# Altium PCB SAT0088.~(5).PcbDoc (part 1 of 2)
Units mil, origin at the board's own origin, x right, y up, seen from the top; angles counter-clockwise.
Board outline 1614.17 x 1181.1 mil, 4 copper layers (Top Layer, InternalPlane1, POWER, Bottom Layer), stack 59 mil thick; 84 components, 49 nets, 273 pads, 217 vias.
Unrouted connection lines stored in the file: 3.
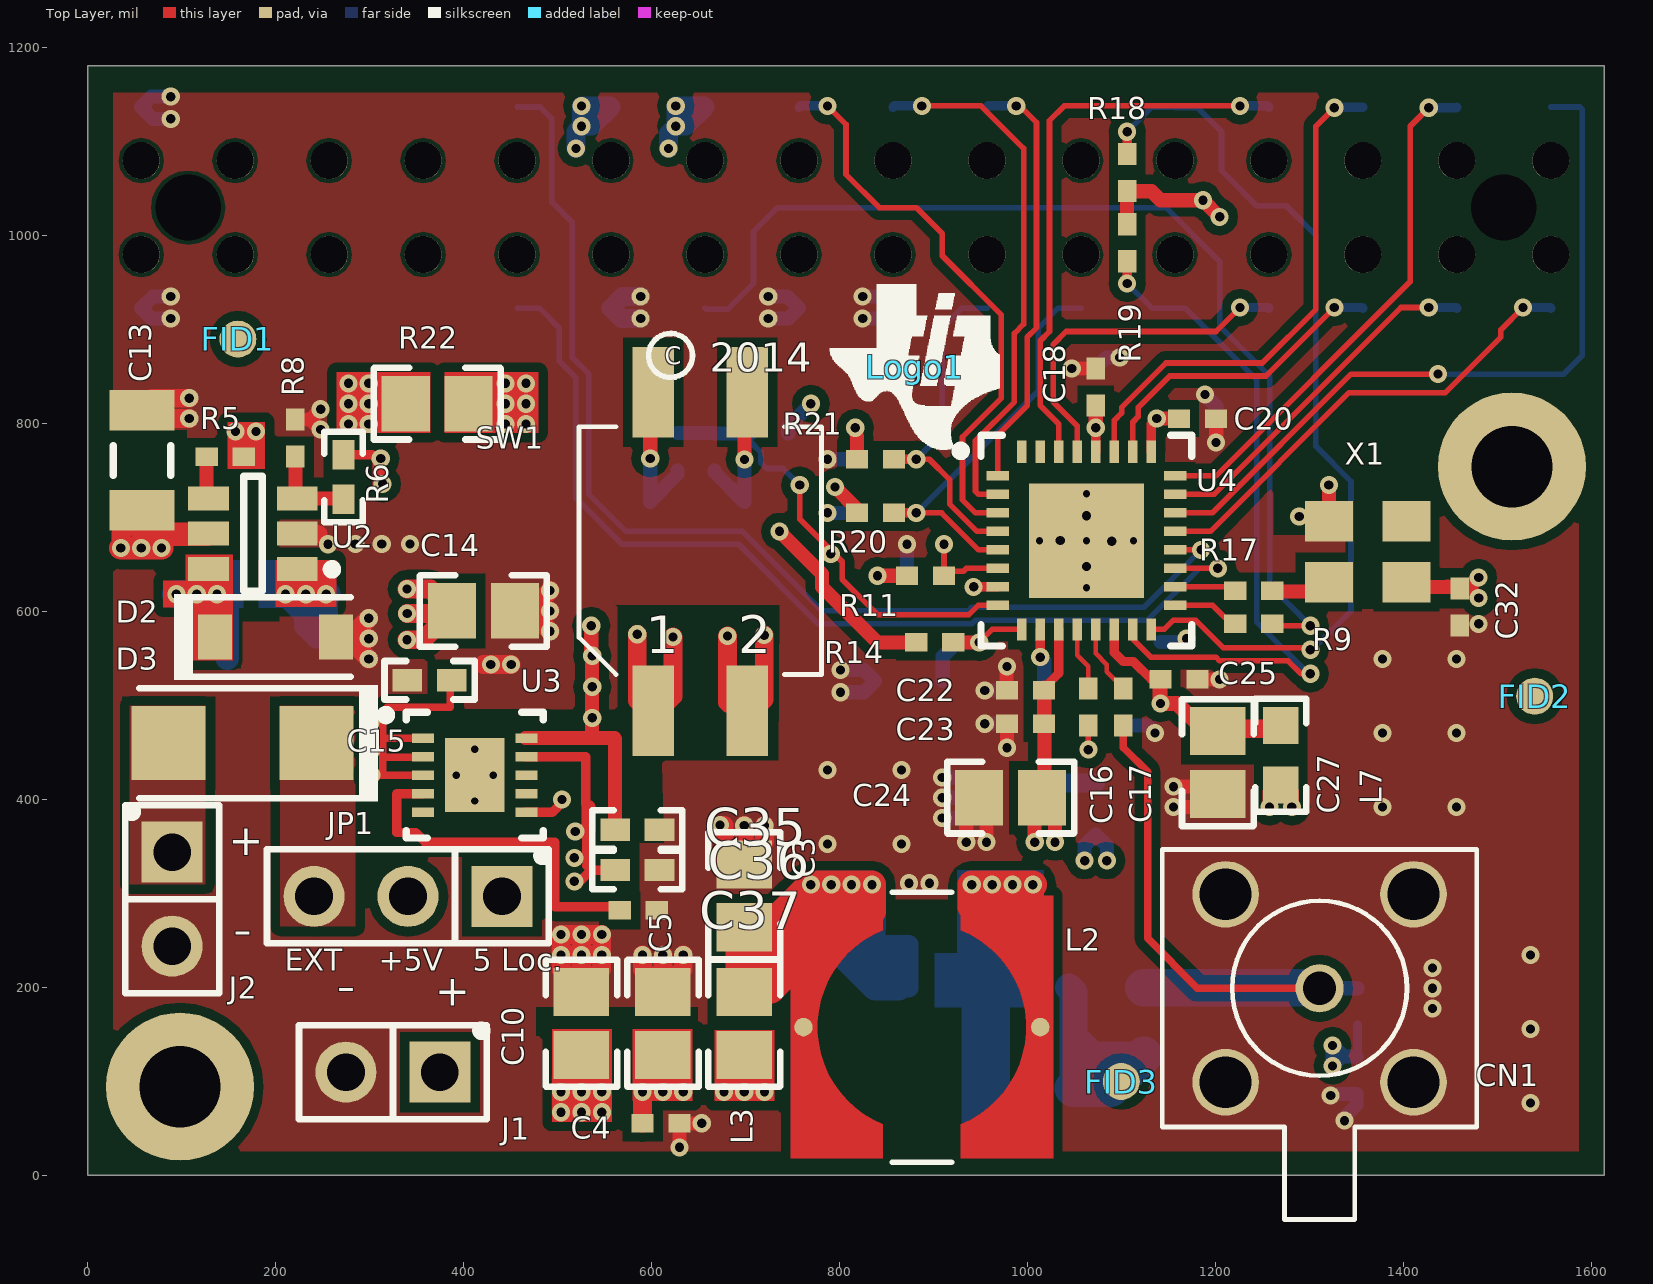
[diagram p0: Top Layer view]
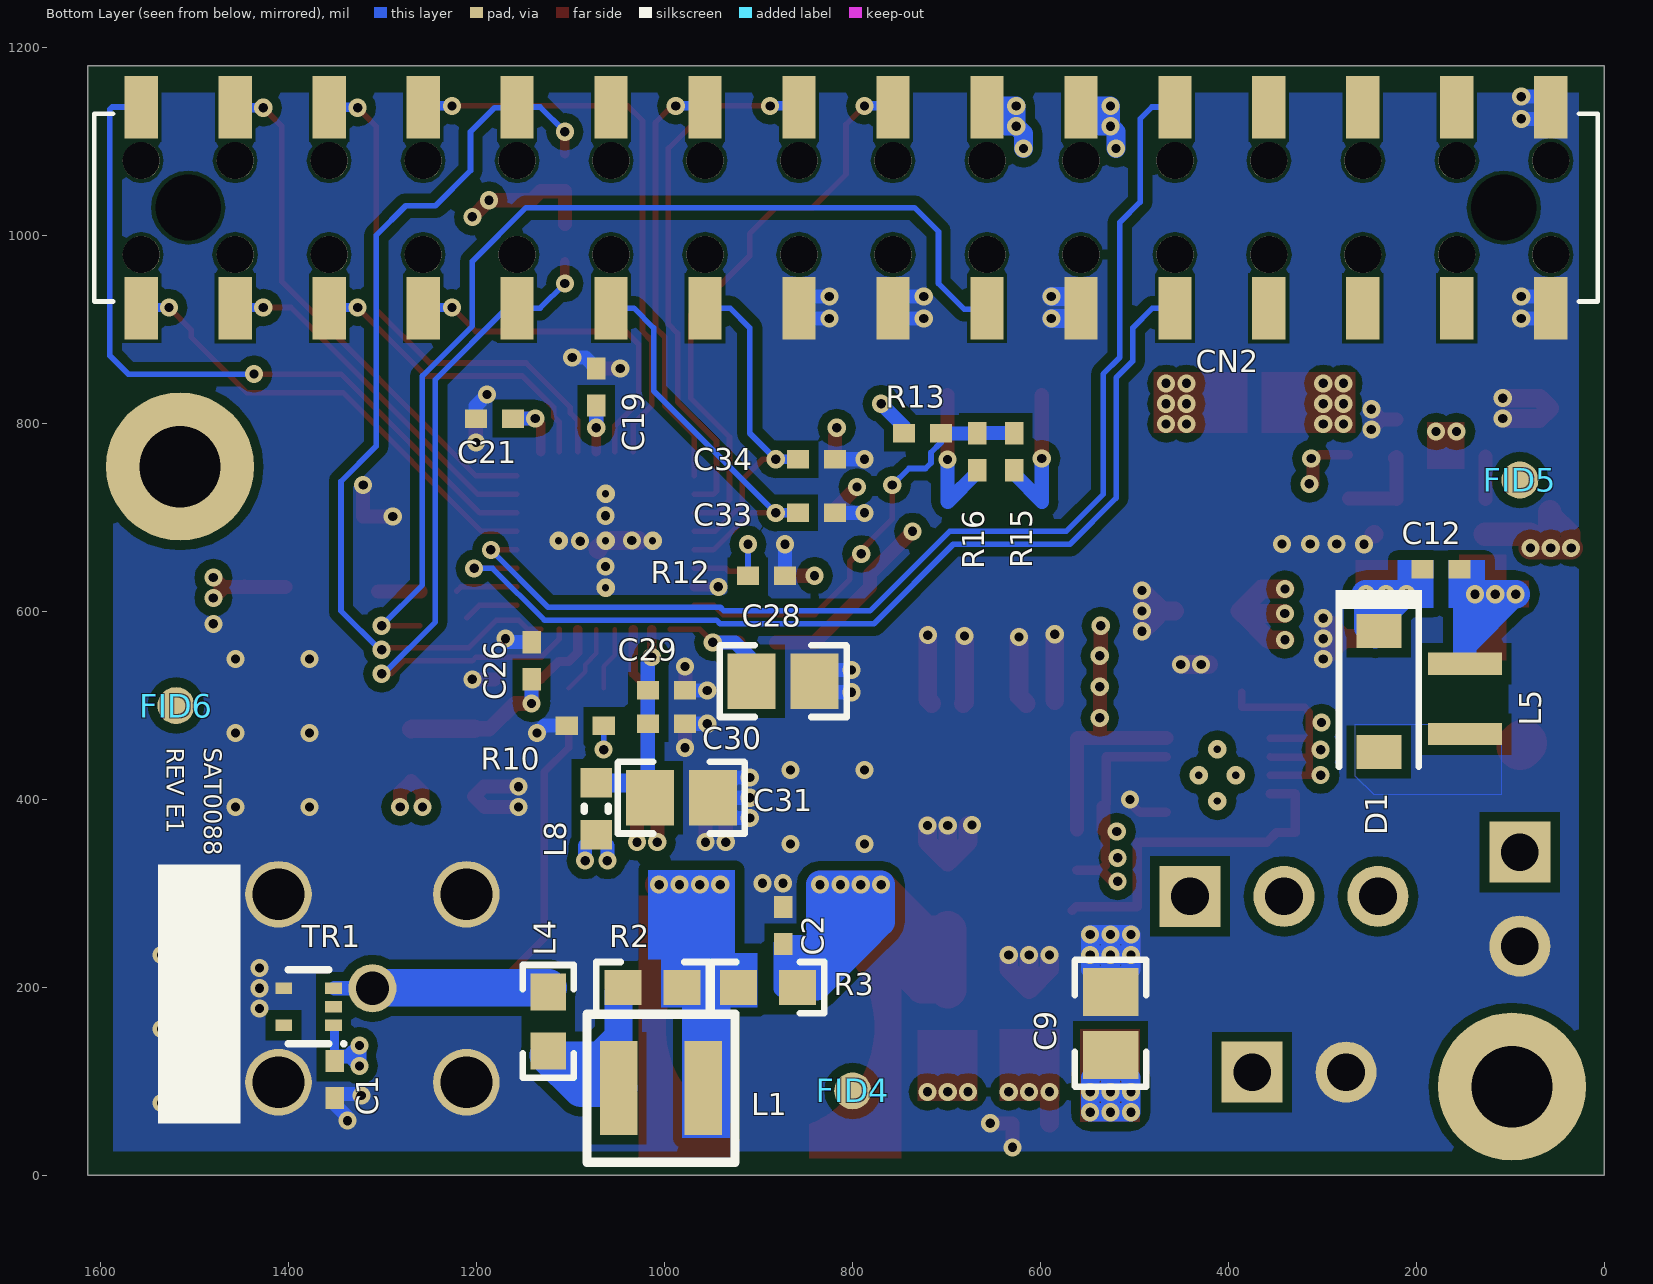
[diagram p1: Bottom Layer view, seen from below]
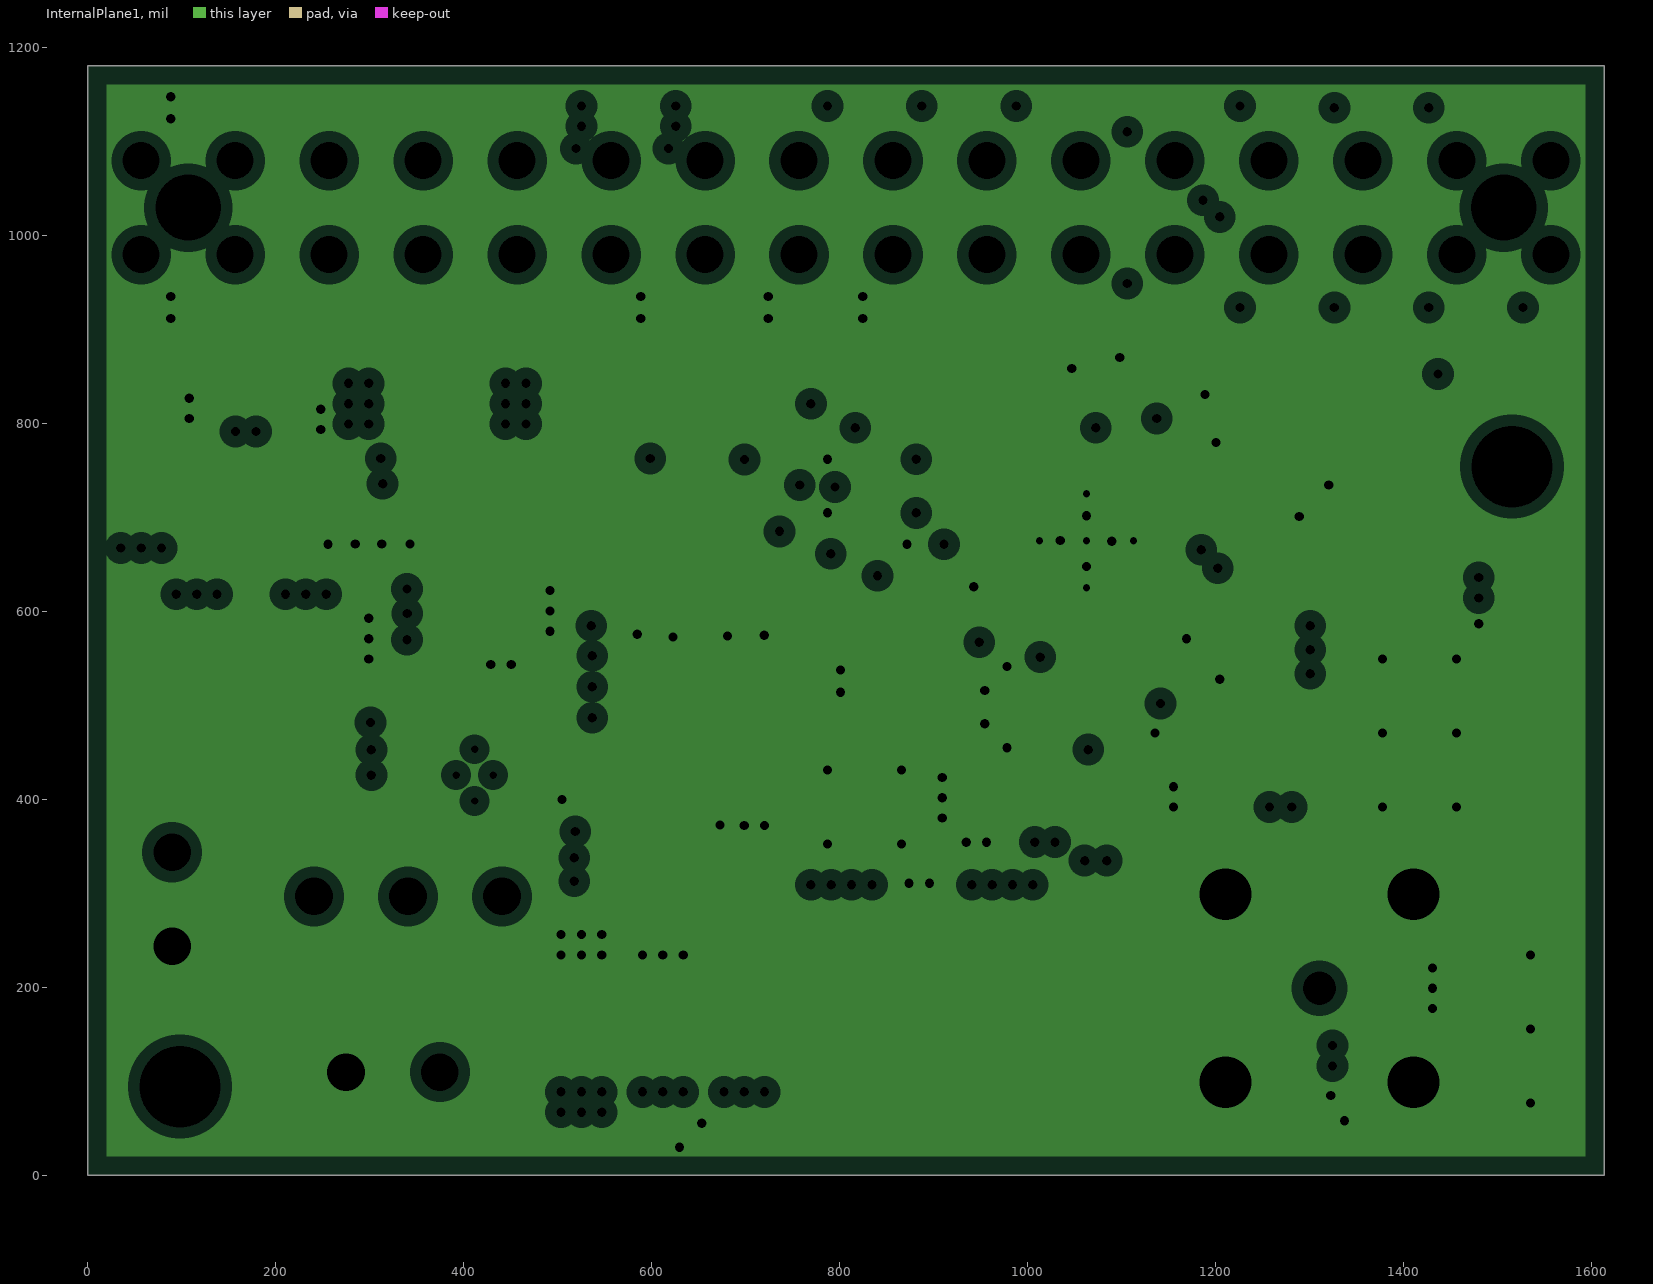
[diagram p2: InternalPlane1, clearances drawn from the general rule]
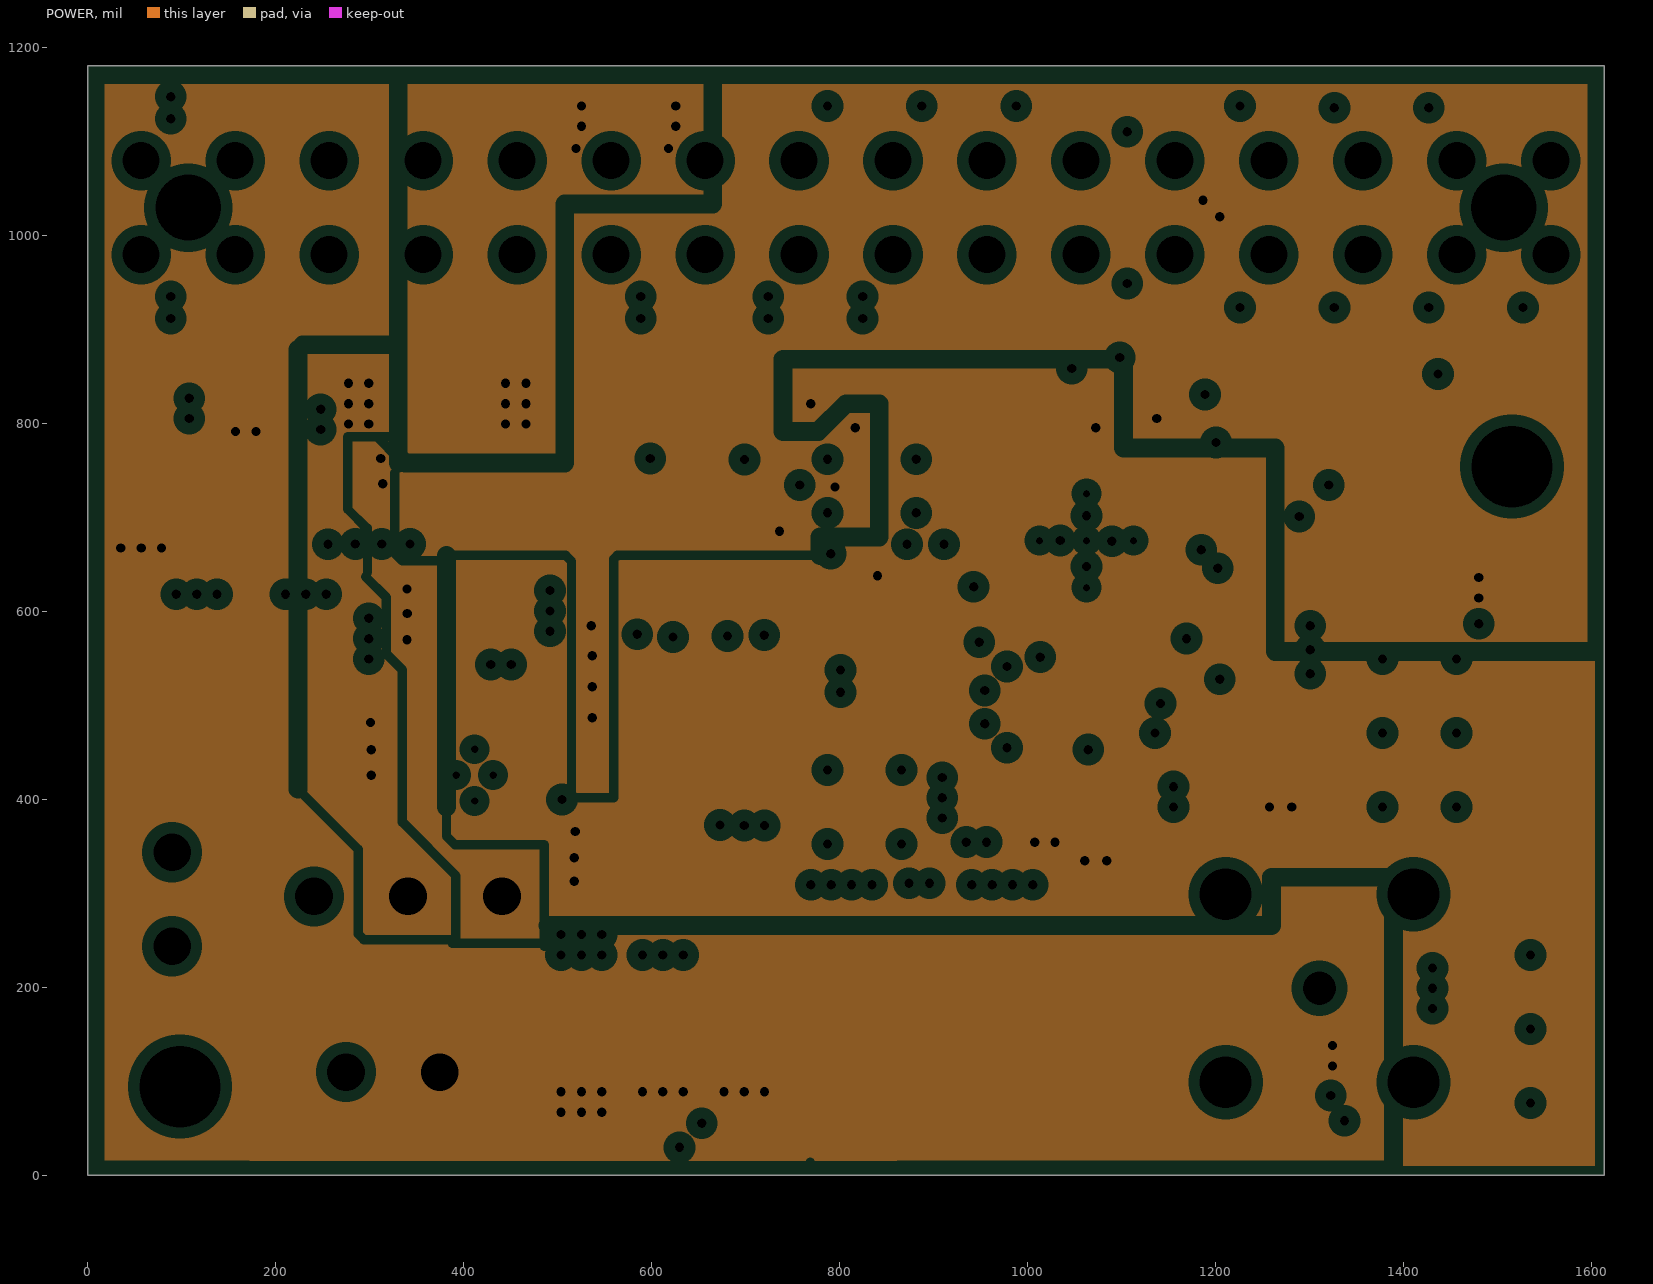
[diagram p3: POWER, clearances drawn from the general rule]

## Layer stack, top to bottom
Top Layer: signal copper 1.4
Dielectric: prepreg 5.2, 370HR, Dk 4.8
InternalPlane1: plane copper 1.4, net DGND
Dielectric: core 43, 370HR, Dk 4.8
POWER: plane copper 1.4, net (Multiple Nets)
Dielectric: prepreg 5.2, 370HR, Dk 4.8
Bottom Layer: signal copper 1.4

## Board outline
0,0 1614.17,0 1614.17,1181.1 0,1181.1

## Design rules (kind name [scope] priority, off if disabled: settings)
AcuteAngle [All] p1: minimum=4.50000000000000E+0001 checktracksonly=FALSE
AssemblyTestPointUsage [All] p1: valid=2
Clearance "Clearance_CN2 holes" [InComponent('CN2')] p1: gap=4
Clearance Clearance_BoardEdge_MountingHoles [OnCopper and InComponentClass('Mounting Holes') vs IsKeepOut] p2: gap=40
Clearance Clearance_BoardEdge_Poly [OnCopper and InPoly vs IsKeepOut] p3: gap=25
Clearance Clearance_BoardEdge [OnCopper and Not InComponentClass('Logo') and not InComponentClass('FiducialMark') and not InRegion(1000,500,4000,800) and Not IsKeepout vs IsKeepOut] p4: gap=25
Clearance Clearance_Poly [InPolygon] p5: gap=10
Clearance [All] p6: gap=5
ComponentClearance ComponentClearance_Logo [InComponentClass('Logo')] p1 off: gap=50 collisioncheckmode=3 verticalgap=10 showdistances=FALSE
ComponentClearance ComponentClearance_ScrewToNut [(HasFootprint('NY PMS 440 0025 PH')) vs (HasFootprint('Keystone_1902C'))] p2 off: gap=5 collisioncheckmode=3 verticalgap=10 showdistances=FALSE
ComponentClearance ComponentClearance_MountingHoles [InComponentClass('Mounting Holes')] p3 off: gap=250 collisioncheckmode=3 verticalgap=100000 showdistances=FALSE
ComponentClearance ComponentClearance_SmallPassives [HasFootprint('0201*') or HasFootprint('0402*') or HasFootprint('0508') or HasFootprint('0603*') or HasFootprint('0612') or HasFootprint('0805*') or HasFootprint('0815*') or HasFootprint('0830*') or HasFootprint('1206*') or HasFootprint('1210*') or HasFootprint('1808*') or HasFootprint('1812*') or HasFootprint('1825*') or HasFootprint('2010*') or HasFootprint('2220*') or HasFootprint('2225*') or HasFootprint('2512*') or HasFootprint('2728*') or HasFootprint('3518*') vs HasFootprint('0201*') or HasFootprint('0402*') or HasFootprint('0508') or HasFootprint('0603*') or HasFootprint('0612') or HasFootprint('0805*') or HasFootprint('0815*') or HasFootprint('0830*') or HasFootprint('1206*') or HasFootprint('1210*') or HasFootprint('1808*') or HasFootprint('1812*') or HasFootprint('1825*') or HasFootprint('2010*') or HasFootprint('2220*') or HasFootprint('2225*') or HasFootprint('2512*') or HasFootprint('2728*') or HasFootprint('3518*')] p4 off: gap=20 collisioncheckmode=3 verticalgap=10 showdistances=FALSE
ComponentClearance ComponentClearance_THtoSMT [IsThruComponent vs IsSMTComponent] p5 off: gap=100 collisioncheckmode=3 verticalgap=30 showdistances=FALSE
ComponentClearance ComponentClearance_THtoTH [IsThruComponent vs IsThruComponent] p6 off: gap=118.11 collisioncheckmode=3 verticalgap=30 showdistances=FALSE
ComponentClearance [All] p7 off: gap=40 collisioncheckmode=3 verticalgap=10 showdistances=FALSE
DiffPairsRouting [All] p1: maxlimit=100 minlimit=10 mostfreqgap=10 maxuncoupledlength=1000
FabricationTestPointUsage TestPointUsage [All] p1: valid=2 allowmultiple=FALSE
FabricationTestpoint Testpoint [All] p1: side=3 testpointundercomponent=TRUE minsize=40 maxsize=100 preferedsize=60 minholesize=0 maxholesize=40 preferedholesize=32 testpointgrid=1 allowsidetop=TRUE allowsidebottom=TRUE usegrid=TRUE gridtolerance=0.01
FanoutControl Fanout_LCC [IsLCC] p1: bgadir=Out bgaviamode=Centered fanoutstyle=Auto fanoutdirection=Alternating viagrid=1 // Fanout_LCC (Default Rule)
FanoutControl Fanout_BGA [IsBGA] p2: bgadir=Out bgaviamode=Centered fanoutstyle=Auto fanoutdirection=Alternating viagrid=1 // Fanout_BGA (Default Rule)
FanoutControl Fanout_Default [All] p4: bgadir=Out bgaviamode=Centered fanoutstyle=Auto fanoutdirection=Alternating viagrid=1 // Fanout_Default (Default Rule)
FanoutControl Fanout_Small [(CompPinCount < 5)] p5: bgadir=Out bgaviamode=Centered fanoutstyle=Auto fanoutdirection=OutThenIn viagrid=1 // Fanout_Small (Default Rule)
HoleSize [All] p1: absolutevalues=TRUE maxlimit=251 minlimit=7.8 maxpercent=80.000 minpercent=20.000
MinimumAnnularRing MinimumAnnularRing_ThermalPadVias [IsVia and InAnyComponent] p1: minimumring=5.91
MinimumAnnularRing [All] p2: minimumring=4.7
MinimumSolderMaskSliver MinimumSolderMaskSliver_Logo [InComponentClass('Logo') vs InComponentClass('Logo')] p1: minsoldermaskwidth=0.7
MinimumSolderMaskSliver [All] p2: minsoldermaskwidth=4
PlaneClearance [All] p1: clearance=12
PlaneConnect [All] p1: planeconnectstyle=Direct reliefexpansion=10 reliefentries=4 reliefconductorwidth=10 reliefairgap=10
PolygonConnect [All] p1: connectstyle=Direct reliefconductorwidth=10 reliefentries=4 polygonreliefangle="90 Angle" airgapwidth=10
RoutingVias ThermalPadVias [IsVia and InAnyComponent] p1: holewidth=7.87 width=19.68 viastyle="Through Hole" minholewidth=7.87 minwidth=19.68 maxholewidth=12.99 maxwidth=23.62
RoutingVias [All] p2: holewidth=16 width=34 viastyle="Through Hole" minholewidth=7.87 minwidth=19 maxholewidth=40 maxwidth=65
SMDToCorner [All] p1: distance=30000
SilkToSilkClearance [All] p1 off: silktosilkclearance=5
SilkscreenOverComponentPads [All] p1: minsilkscreentomaskgap=1
SolderMaskExpansion [All] p1: expansion=1
Width [All] p1: maxlimit=100 minlimit=5 preferedwidth=10 minimp=50.000000 maximp=50.000000 favimp=50.000000 checkconnectedcopper=TRUE
13 further rules are at their usual default settings.

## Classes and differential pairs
component class AssemblyNote: ZZ1 ZZ2 ZZ3 ZZ4
component class FiducialMark: FID1 FID2 FID3 FID4 FID5 FID6
component class Logo: Logo1
component class CAMERA_PORT: C33 C34 CN2 R18 R19 R20 R21 R22
component class Hardware: !PCB FID1 FID2 FID3 FID4 FID5 FID6 Logo1 ZZ1 ZZ2 ZZ3 ZZ4
component class Header: J1 J2 JP1
component class HF_PORT: C1 C2 C3 C4 C5 CN1 L1 L2 L3 L4 R2 R3 TR1
component class POWER: C9 C10 C12 C13 C14 C15 C35 C36 C37 D1 D2 D3 J1 J2 JP1 L5 R5 R6 R8 U2 U3
component class SERIALIZER: C16 C17 C18 C19 C20 C21 C22 C23 C24 C25 C26 C27 C28 C29 C30 C31 C32 L7 L8 R9 R10 R11 R12 R13 R14 R15 R16 R17 SW1 U4 X1

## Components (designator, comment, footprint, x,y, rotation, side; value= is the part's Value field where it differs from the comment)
C1 "C1005X7R1H104K050BB" 0402L 1351,102 r270 bottom
C2 "GRM155R71C104KA88D" 0402L 874.02,266.14 r90 bottom
C3 "GRM21BR71C475KA73L" 0805 698.82,297.64 r90 top
C4 "GRM155R71C104KA88D" 0402L 610.24,55.51 r0 top
C5 "GRM21BR71C475KA73L" 0805 612.2,161.81 r90 top
C9 "C2012X5R1C226K125AC" 0805 525.59,161.81 r90 bottom
C10 "C2012X5R1C226K125AC" 0805 525.59,161.81 r90 top
C12 "GRM155R71H103KA88D" 0402L 174.02,644.88 r180 bottom
C13 "GRM31CR71E106KA12L" 1206L 57.87,761.02 r90 top
C14 "C2012X5R1C226K125AC" 0805 421.26,600.79 r0 top
C15 "GRM155R61A105KE15D" 0402 364,527 r180 top
C16 "CGA2B3X7R1H473K050BB" 0402L 1064.96,498.43 r90 top
C17 "C1005X7R1H104K050BB" 0402L 1102.36,498.43 r90 top
C18 "C1005X7R1C103K" 0402L 1072.83,838.98 r90 top
C19 "GRM155R71C104KA88D" 0402L 1072.83,838.98 r90 bottom
C20 "C1005X7R1C103K" 0402L 1181.1,805.51 r0 top
C21 "GRM155R71C104KA88D" 0402L 1181.1,805.51 r0 bottom
C22 "C1005X7R1C103K" 0402L 998.03,516.14 r180 top
C23 "GRM155R71C104KA88D" 0402L 998.03,480.71 r180 top
C24 "GRM21BR71C475KA73L" 0805 982.28,401.97 r180 top
C25 "C1005X7R1C103K" 0402L 1161.42,527.95 r0 top
C26 "GRM155R71C104KA88D" 0402L 1141.73,547.64 r90 bottom
C27 "C2012X5R1C226K125AC" 0805 1202.76,439.37 r270 top
C28 "C2012X5R1C226K125AC" 0805 874.02,525.98 r180 bottom
C29 "C1005X7R1C103K" 0402L 998.03,516.14 r180 bottom
C30 "GRM155R71C104KA88D" 0402L 998.03,480.71 r180 bottom
C31 "GRM21BR71C475KA73L" 0805 982.28,401.97 r180 bottom
C32 "GRM155R71C104KA88D" 0402L 1460,605 r270 top
C33 "C0402C100K4GACTU" 0402L 838.58,705.12 r180 bottom
C34 "C0402C100K4GACTU" 0402L 838.58,762.2 r180 bottom
C35 "GRM155R61A105KE15D" 0402 585,368 r0 top
C36 "GRM155R61A105KE15D" 0402 585,325 r0 top
C37 "GRM155R71H103KA88D" 0402L 586,282 r180 top
CN1 "59S10H-40ML5-Y" 59S10H-40ML5-Y 1311.02,199.21 r270 top
CN2 "HLE-116-02-F-DV-PE-BE" HLE-116-02-F-DV-PE-BE 807.09,1029.92 r0 bottom
D1 "MBRX140-TP" SOD-123 240,515 r270 bottom
D2 "MBRX140-TP" SOD-123 200,573 r0 top
D3 "B120-13-F" SMA 165,460 r180 top
FID1 "Fiducial" Fiducial10-20 160,890 r0 top
FID2 "Fiducial" Fiducial10-20 1540,510 r0 top
FID3 "Fiducial" Fiducial10-20 1100,100 r0 top
FID4 "Fiducial" Fiducial10-20 800,90 r180 bottom
FID5 "Fiducial" Fiducial10-20 90,740 r180 bottom
FID6 "Fiducial" Fiducial10-20 1520,500 r180 bottom
J1 "TSW-102-07-G-S" TSW-102-07-G-S 325,110 r180 top
J2 "TSW-102-07-G-S" TSW-102-07-G-S 90,294 r270 top
JP1 "TSW-103-07-G-S" TSW-103-07-G-S 341,297 r180 top
L1 "1008PS-472KLB" 1008PS-472KLB 1003.94,92.91 r0 bottom
L2 "MSS7341T-104MLB" MSS7341T-104MLB 887.8,157.87 r270 top
L3 "MPZ2012S102A" 0805 698.82,161.81 r270 top
L4 "BLM18SG121TN1D" 0603 1124,164 r90 bottom
L5 "LQM2HPN3R3MG0L" IND_1008 148.43,507.09 r270 bottom
L7 "BK1608HW601-T" 0603 1269.68,447.24 r270 top
L8 "BK1608HW601-T" 0603L 1072.83,390.16 r270 bottom
Logo1 "Texas Instruments" TI_Symbol_Overlay_Small 880,860 r0 top
R2 "RC0603FR-071KL" 0603 1013,200 r0 bottom
R3 "RC0603FR-071KL" 0603 890,200 r0 bottom
R5 "CRCW040210K0FKED" 0402L 146.46,764.96 r180 top
R6 "CRCW040252K3FKED" 0402 272.44,743.31 r90 top
R8 "CRCW040210K0FKED" 0402L 221.26,784.65 r90 top
R9 "CRCW040233R0JNED" 0402L 1241,587 r180 top
R10 "CRCW040249R9FKED" 0402L 1084.65,478.74 r0 bottom
R11 "CRCW040210K0FKED" 0402L 891.73,638.19 r0 top
R12 "CRCW04020000Z0ED" 0402L 891.73,638.19 r180 bottom
R13 "CRCW040210K0FKED" 0402L 725.59,789.76 r180 bottom
R14 "CRCW040210K0FKED" 0402L 901.57,567.32 r0 top
R15 "CRCW0402100KFKED" 0402L 627.95,770.08 r90 bottom
R16 "CRCW04024K75FKED" 0402L 667.32,770.08 r270 bottom
R17 "CRCW04020000Z0ED" 0402L 1241,622 r0 top
R18 "CRCW04022K20JNED" 0402L 1106.3,1067.32 r90 top
R19 "CRCW04022K20JNED" 0402L 1106.3,992.52 r270 top
R20 "CRCW04022K20JNED" 0402L 838.58,705.12 r0 top
R21 "CRCW04022K20JNED" 0402L 838.58,762.2 r0 top
R22 "CRCW08050000Z0EA" 0805 372.05,821.26 r0 top
SW1 "219-2LPST" SW_219-2LPST 652,664 r90 top
TR1 "TPD2E001DRLR" DRL0005A 1378.95,179.53 r0 bottom
U2 "LM2734ZMK/NOPB" MK06A_N 176,683 r180 top
U3 "LP3996SD-1833/NOPB" SDA10A 412,426 r0 top
U4 "DS90UB913ATRTVTQ1" RTV0032A 1062.99,675.59 r0 top
X1 "ASE-48.000MHZ-LC-T" ASE-48.000MHZ-LC-T 1362.2,663.78 r180 top
ZZ1 "This Assembly Note is for PCB labels only" AssemblyNoteLabel 85,1698 r0 top
ZZ2 "These assemblies are ESD sensitive, ESD precautions shall be observed." AssemblyNote 85,1589.11 r0 top
ZZ3 "These assemblies must be clean and free from flux and all contaminants. Use of no clean flux is not acceptable." AssemblyNote 85,1500.56 r0 top
ZZ4 "These assemblies must comply with workmanship standards IPC-A-610 Class 2, unless otherwise specified." AssemblyNote 85,1412 r0 top

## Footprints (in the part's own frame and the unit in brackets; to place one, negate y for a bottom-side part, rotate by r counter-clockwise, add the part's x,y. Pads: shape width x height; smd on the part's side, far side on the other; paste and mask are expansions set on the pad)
59S10H-40ML5-Y [mm] "Rosenberger Straight Plug"
  round 1.3 hole 0.9: 1(0,0)
  round 1.8 hole 1.4: 2(-2.54,2.54) 3(-2.54,-2.54) 4(2.54,-2.54) 5(2.54,2.54)
  silkscreen extent -3.75,-4.25 6.25,4.25
0402 [mm] "0402 from SM-752 data"
  rect 0.8x0.6 smd: 1(-0.6,0) 2(0.6,0)
  silkscreen extent -1.22,-0.52 1.22,0.52, body extent -0.55,-0.3 0.55,0.3, height 0.6
0402L [mm] "0402 from SM-752 data"
  rect 0.6x0.5 smd: 1(-0.5,0) 2(0.5,0)
  body extent -0.55,-0.3 0.55,0.3, height 0.6
0603 [mm] "0603 from SM-752 data"
  rect 1x0.95 smd: 1(-0.8,0) 2(0.8,0)
  silkscreen extent -1.52,-0.69 1.52,0.69, body extent -0.87,-0.47 0.87,0.47, height 0.85
0603L [mm] "0603 from SM-752 data"
  rect 0.8x0.85 smd: 1(-0.7,0) 2(0.7,0)
  silkscreen extent -0.07,-0.33 0.07,0.33, body extent -0.87,-0.47 0.87,0.47, height 0.85
0805 [mm] "0805 from SM-752 data"
  rect 1.3x1.5 smd: 1(-0.85,0) 2(0.85,0)
  silkscreen extent -1.72,-0.97 1.72,0.97, body extent -1.1,-0.72 1.1,0.72, height 1.1
1008PS-472KLB [mil] "Coilcraft Inductor"
  rect 40.16x100 smd: 1(-45,0) 2(45,0)
  silkscreen extent -79,-79 79,79, body extent -75,-75 75,75, height 108
1206L [mm] "1206 from SM-752 data"
  rect 1.1x1.75 smd: 1(-1.35,0) 2(1.35,0)
  silkscreen extent -0.4,-0.77 0.4,0.77, body extent -1.7,-0.9 1.7,0.9, height 1.35
ASE-48.000MHZ-LC-T [mm] "2.5mm x 3.2mm"
  rect 1.3x1.1 smd: 1(-1.05,-0.825) 2(1.05,-0.825) 3(1.05,0.825) 4(-1.05,0.825)
  body extent -1.6,-1.25 1.6,1.25, height 0.91
AssemblyNote [mil] "Assembly Note"
AssemblyNoteLabel [mil] "Assembly Note for PCB Labels"
DRL0005A [mm] "SOTFL, 5-Flat Leads, Body 1.2x1.6x0.6mm, Pitch 0.5mm, TI Recommended"
  rect 0.45x0.3 smd: 1(-0.675,0.5) 2(-0.675,0) 3(-0.675,-0.5) 4(0.675,-0.5) 5(0.675,0.5)
  silkscreen extent -1,-1 0.55,1.05, body extent -0.65,-0.85 0.65,0.85, height 0.6
Fiducial10-20 [mm]
  round 1 smd paste-0.5 mask+0.5: 1(0,0)
HLE-116-02-F-DV-PE-BE [mm] "Samtec Pass Through for Bottom Entry"
  rect 0.9x1.686 smd: 1(19.05,-2.718) 2(19.05,2.718) 3(16.51,-2.718) 4(16.51,2.718) 5(13.97,-2.718) 6(13.97,2.718) 7(11.43,-2.718) 8(11.43,2.718) 9(8.89,-2.718) 10(8.89,2.718) 11(6.35,-2.718) 12(6.35,2.718) 13(3.81,-2.718) 14(3.81,2.718) 15(1.27,-2.718) 16(1.27,2.718) 17(-1.27,-2.718) 18(-1.27,2.718) 19(-3.81,-2.718) 20(-3.81,2.718) 21(-6.35,-2.718) 22(-6.35,2.718) 23(-8.89,-2.718) 24(-8.89,2.718) 25(-11.43,-2.718) 26(-11.43,2.718) 27(-13.97,-2.718) 28(-13.97,2.718) 29(-16.51,-2.718) 30(-16.51,2.718) 31(-19.05,-2.718) 32(-19.05,2.718)
  round 1 hole 1 unplated: ""(-19.05,-1.27) ""(-19.05,1.27) ""(-16.51,-1.27) ""(-16.51,1.27) ""(-13.97,-1.27) ""(-13.97,1.27) ""(-11.43,-1.27) ""(-11.43,1.27) ""(-8.89,-1.27) ""(-8.89,1.27) ""(-6.35,-1.27) ""(-6.35,1.27) ""(-3.81,-1.27) ""(-3.81,1.27) ""(-1.27,-1.27) ""(-1.27,1.27) ""(1.27,-1.27) ""(1.27,1.27) ""(3.81,-1.27) ""(3.81,1.27) ""(6.35,-1.27) ""(6.35,1.27) ""(8.89,-1.27) ""(8.89,1.27) ""(11.43,-1.27) ""(11.43,1.27) ""(13.97,-1.27) ""(13.97,1.27) ""(16.51,-1.27) ""(16.51,1.27) ""(19.05,-1.27) ""(19.05,1.27)
  round 0 hole 1.78 unplated: ""(-17.78,0) ""(17.78,0)
  silkscreen extent -20.32,-2.54 20.32,2.54
IND_1008 [mm]
  rect 0.6x2 smd: 1(-0.95,0) 2(0.95,0)
MK06A_N [mm] "SOT23, 6-Leads, Body 3.0x1.7mm, Pitch 0.95mm, Lead Span 2.9mm, IPC Medium Density"
  rect 1.1x0.65 smd: 1(-1.2,0.95) 2(-1.2,0) 3(-1.2,-0.95) 4(1.2,-0.95) 5(1.2,0) 6(1.2,0.95)
  silkscreen extent -2.26,-1.55 0.25,1.55, body extent -0.9,-1.55 0.9,1.55, height 1
MSS7341T-104MLB [mm]
  round 0.5 smd mask+0: 1(0,3.2) 2(0,-3.2)
  Top Layer region: -3.55,1.05 -3.55,3.55 3.55,3.55 3.55,1.05 2.623,1.05 1.85,2.135 0.666,2.745 -0.666,2.745 -1.85,2.135 -2.623,1.05 -2.623,1.05
  Top Layer region: -3.55,-3.55 -3.55,-1.05 -2.623,-1.05 -1.85,-2.135 -0.666,-2.745 0.666,-2.745 1.85,-2.135 2.623,-1.05 2.623,-1.05 3.55,-1.05 3.55,-3.55
  silkscreen extent -3.65,-0.8 3.65,0.8, body extent -3.66,-3.56 3.66,3.56, height 4.1
RTV0032A [mm] "QFN, 32-Leads, Body 5x5mm, Pitch 0.5mm"
  rect 0.6x0.25 smd: 1(-2.4,1.75) 2(-2.4,1.25) 3(-2.4,0.75) 4(-2.4,0.25) 5(-2.4,-0.25) 6(-2.4,-0.75) 7(-2.4,-1.25) 8(-2.4,-1.75) 17(2.4,-1.75) 18(2.4,-1.25) 19(2.4,-0.75) 20(2.4,-0.25) 21(2.4,0.25) 22(2.4,0.75) 23(2.4,1.25) 24(2.4,1.75)
  rect 0.25x0.6 smd: 9(-1.75,-2.4) 10(-1.25,-2.4) 11(-0.75,-2.4) 12(-0.25,-2.4) 13(0.25,-2.4) 14(0.75,-2.4) 15(1.25,-2.4) 16(1.75,-2.4) 25(1.75,2.4) 26(1.25,2.4) 27(0.75,2.4) 28(0.25,2.4) 29(-0.25,2.4) 30(-0.75,2.4) 31(-1.25,2.4) 32(-1.75,2.4)
  rect 3.1x3.1 smd paste-1.55: 33(0,0)
  silkscreen extent -3.52,-2.85 2.85,2.85, body extent -2.55,-2.55 2.55,2.55, height 0.81
SDA10A [mm] "SON, 10-Leads, Body 3x3 mm, Pitch 0.5mm, NSC Recommended"
  rect 0.6x0.25 smd paste-0.125 mask+0.051: 1(-1.4,1) 2(-1.4,0.5) 3(-1.4,0) 4(-1.4,-0.5) 5(-1.4,-1) 6(1.4,-1) 7(1.4,-0.5) 8(1.4,0) 9(1.4,0.5) 10(1.4,1)
  rect 1.6x2 smd paste-0.05 mask+0.051: 11(0,0)
  silkscreen extent -2.52,-1.7 1.85,1.75, body extent -1.55,-1.55 1.55,1.55, height 0.8
SMA [mm] "Molded Diode, 2-Leads, Body 4.3x2.6mm, IPC Medium Density, based on OnSemi component dimensions and land pattern"
  rect 2x2 smd: 1(-2,0) 2(2,0)
  silkscreen extent -3.66,-1.57 2.79,1.57, body extent -2.6,-1.3 2.6,1.3, height 2.42
SOD-123 [mm] "On Semi recommended land pattern"
  rect 0.915x1.22 smd: 1(-1.637,0) 2(1.637,0)
  silkscreen extent -2.74,-1.17 2.03,1.17, body extent -1.93,-0.9 1.93,0.9, height 1.35
SW_219-2LPST [mm] "SW, Tape Seal, 2 POS, SMD"
  rect 2.44x1.12 smd: 1(-4.305,1.27) 2(-4.305,-1.27) 3(4.305,-1.27) 4(4.305,1.27)
  silkscreen extent -3.32,-3.27 3.38,3.27, body extent -4.95,-3.28 4.96,3.27, height 4.25
TI_Symbol_Overlay_Small [mil]
  silkscreen extent -90,-88 91,88
TSW-102-07-G-S [mm] "Samtec 100mil, 1x2, 230 mil above insulator"
  rect 1.65x1.65 hole 1.016 mask+0: 1(-1.27,0)
  round 1.65 hole 1.016 mask+0: 2(1.27,0)
  silkscreen extent -2.54,-1.27 2.54,1.27, body extent -2.54,-1.27 2.54,1.27, height 8.38
TSW-103-07-G-S [mm] "Samtec 100mil, 1x3, 230 mil above insulator"
  rect 1.65x1.65 hole 1.016 mask+0: 1(-2.54,0)
  round 1.65 hole 1.016 mask+0: 2(0,0) 3(2.54,0)
  silkscreen extent -3.81,-1.27 3.81,1.27, body extent -3.81,-1.27 3.81,1.27, height 8.38

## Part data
C1 C17: "CAP, CERM, 0.1uF, 50V, +/-10%, X7R, 0402"
C2 C4 C19 C21 C23 C26 C30 C32: "CAP, CERM, 0.1uF, 16V, +/-10%, X7R, 0402"
C3 C5 C24 C31: "CAP, CERM, 4.7uF, 16V, +/-10%, X7R, 0805"
C9 C10 C14 C27 C28: "CAP, CERM, 22uF, 16V, +/-10%, X5R, 0805"
C12 C37: "CAP, CERM, 0.01uF, 50V, +/-10%, X7R, 0402"
C13: "CAP, CERM, 10uF, 25V, +/-10%, X7R, 1206"
C15 C35 C36: "CAP, CERM, 1uF, 10V, +/-10%, X5R, 0402"
C16: library part Capacitor, "CAP, CERM, 0.047uF, 50V, X7R, 10%, 0402"
C18 C20 C22 C25 C29: "CAP, CERM, 0.01uF, 16V, +/-10%, X7R, 0402"
C33 C34: library part Capacitor, "CAP, CERM, 10pF, 16V, NP0, 10%, 0402"
CN1: "Straight Plug PCB"
CN2: "Samtec .100\" Tiger Beam Socket Strip"
D1 D2: library part Diode_Schottky, "Diode, Schottky, 40V, 1A, SOD-123"
D3: "Diode, Schottky, 20V, 1A, SMA"
FID1 FID2 FID3 FID4 FID5 FID6: "Fiducial mark.  There is nothing to buy or mount."
J1 J2: "Header, TH, 100mil, 2x1, Gold plated, 230 mil above insulator"
JP1: "Header, TH, 100mil, 3x1, Gold plated, 230 mil above insulator"
L1: "Fixed Inductors Power Inductor 4.7 uH 10 % 0.95 A"
L2: "Fixed Inductors Power Inductor 100 uH 20 % 1.15 A"
L3: library part Ferrite_Bead, "1.5A Ferrite Bead, 1000ohm @ 100MHz"
L4: "3A Ferrite Bead, 120 ohm @ 100MHz, SMD"
L5: library part Inductor, "Inductor, Shielded 3.3uH, 1200mA, 100 mohm, Surface Mount"
L7 L8: library part Ferrite_Bead, "300mA Ferrite Bead, 600 ohm @ 100MHz"
Logo1: library part TI_Logo, "Texas Instrument Corporate Signature"
R2 R3: "RES, 1.00k ohm, 1%, 0.1W, 0603"
R5 R8 R11 R13 R14: "RES, 10.0k ohm, 1%, 0.063W, 0402"
R6: "RES, 52.3k ohm, 1%, 0.063W, 0402"
R9: "RES, 33 ohm, 5%, 0.063W, 0402"
R10: "RES, 49.9 ohm, 1%, 0.063W, 0402"
R12 R17: "RES, 0 ohm, 5%, 0.063W, 0402"
R15: "RES, 100k ohm, 1%, 0.063W, 0402"
R16: "RES, 4.75k ohm, 1%, 0.063W, 0402"
R18 R19 R20 R21: "RES, 2.2k ohm, 5%, 0.063W, 0402"
R22: "RES, 0 ohm, 5%, 0.125W, 0805"
SW1: "Switch, Slide, SPST 2 poles, SMT"
TR1: "Low-Capacitance + / - 15 kV ESD-Protection Array for High-Speed Data Interfaces, 2 Channels, -40 to +85 degC, 5-pin SOT (DRL), Green (RoHS & no Sb/Br)"
U2: "1A Load Step-Down DC-DC Regulator, 6-pin Tiny SOT23, Pb-Free"
U3: "Dual Linear Regulator with 300mA and 150mA Outputs and Power-On-Reset, 10-pin LLP, Pb-Free"
U4: "DS90UB913A-Q1/DS90UB914A-Q1 25 to 100 MHz 10/20-Bit FPD-Link III Serializer and Deserializer, RTV0032A"
X1: "OSC XO 48.00MHZ CMOS SMD"
ZZ1: library part AssemblyNoteLabel
ZZ2 ZZ3 ZZ4: library part AssemblyNote

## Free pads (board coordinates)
  round 157.48 hole 86.61: 12(98.43,94.49) 12(1515.75,754.33)

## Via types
v1: diameter 19.29, hole 9.84, Top Layer to Bottom Layer, tented both sides, 208 vias
v2: diameter 19.68, hole 7.87, Top Layer to Bottom Layer, 5 vias
v3: diameter 19.68, hole 7.87, Top Layer to Bottom Layer, tented top, 4 vias

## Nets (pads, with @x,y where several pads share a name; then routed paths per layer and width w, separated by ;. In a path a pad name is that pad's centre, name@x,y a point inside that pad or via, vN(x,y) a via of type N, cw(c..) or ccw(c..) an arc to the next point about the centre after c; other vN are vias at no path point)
+1V8: C18.1 C19.1 C22.1 C23.1 C24.1 C36.1 L7.2 L8.2 R11.1 R13.1 U3.9 U4.11 U4.28 | length 819.8
  Top Layer w9.84: 1033.46,561.42 U4.11@1033.46,581.1 ; U4.28@1072.83,770.08 v1(1072.83,795.67)
  Top Layer w10: U3.9@466.12,445.68 530.32,445.68 530.32,395.06 533.13,392.25 ; v1(518,313) 524,313 536,325 ; v1(518,338) 530.13,338 531.13,337 531.13,366 ; v1(519,366) 531.13,366 ; 531.13,329.87 536,325 ; 533.13,368 531.13,366 ; C36.1@561.38,325 536,325 ; C22.1@1018.03,519.03 1033.46,534.46 1033.46,561.42
  Top Layer w15: 533.13,368 533.13,392.25 ; v1(840.55,638.19) R11.1@871.73,638.19 ; v1(1007.87,354.72) 1007.87,391.56 1017.02,400.7 C24.1@1018.28,401.97 ; C22.1@1018.03,519.03 1018.03,480.71 1018.28,480.46 C24.1@1018.28,401.97 ; v1(1029.53,354.72) 1029.53,390.72 C24.1@1018.28,401.97 ; v1(1072.83,795.67) C18.1@1072.83,818.98 ; v1(1257.87,392.13) 1257.87,407.93 1269.68,419.74 1271.68,417.75 1281.5,407.93 v1(1281.5,392.13)
  Bottom Layer w15: R13.1@745.59,789.76 745.59,797.17 v1(769.68,821.26) ; v1(1061.02,335.04) 1061.02,350.85 1072.83,362.66 1074.83,360.66 1084.65,350.85 v1(1084.65,335.04) ; v1(1072.83,795.67) C19.1@1072.83,818.98
+3V3: C20.1 C21.1 C32.1 C35.1 R14.1 R18.1 R19.1 R20.1 R21.1 U3.10 U4.25 X1.4 | length 912
  Top Layer w9.84: U4.25@1131.89,770.08 1131.89,799.61 v1(1137.8,805.51)
  Top Layer w15: U3.10@466.12,465.37 537,465.37 ; v1(536,585) 536,554 v1(537,553) 537,465.37 ; C35.1@561.38,368 561.38,464.62 560.63,465.37 537,465.37 ; v1(736.22,685.43) 781.5,640.16 781.5,626.38 840.55,567.32 R14.1@881.57,567.32 ; v1(795.28,732.68) 818.58,709.37 R20.1@818.58,705.12 ; v1(816.93,795.67) 818.58,786.14 R21.1@818.58,762.2 ; R19.1@1106.3,1012.52 1106.3,1047.32 1132.2,1047.32 1141.73,1037.8 v1(1187.01,1037.8) v1(1204.72,1020.08) ; v1(1137.8,805.51) C20.1@1161.1,805.51 ; X1.4@1403.54,626.38 1446.54,626.38 1446.85,626.69 1447.01,626.54 1447.48,626.06 C32.1@1468.82,626.06 ; v1(1480.32,614.57) 1469.49,625.39 C32.1@1468.82,626.06 ; v1(1480.32,636.22) 1470.16,626.06 C32.1@1468.82,626.06
  Bottom Layer w15: v1(1137.8,805.51) C21.1@1161.1,805.51
  other v1: 537,487 537,520
+5V: C15.1 JP1.2 R22.1 U3.1 U3.2 U3.3 | length 348.6
  Top Layer w8: v1@297,455 313,455 ; v1(301,482) 297,482 314,482 ; v1(302,426) 297,426 314,426 ; 314,454 314,445 ; 314,455 314,464 ; U3.3@355.88,426 314,426 ; U3.2@355.88,445.68 355.2,445 314,445 ; U3.1@355.88,465.37 315.37,465.37 314,464 ; 386,514 386,498 319,498 314,493 314,482 ; 314,426 314,445 ; 314,464 314,482
  Top Layer w10: JP1.2@341,297 JP1.2@341,304
  other v1: 302,453 277.56,799.61 299.21,799.61 277.56,821.26 299.21,821.26 277.56,842.91 299.21,842.91
+5V_EXT: D3.1 JP1.3
+5V_LOCAL: C14.1 D1.2 JP1.1 L5.2 R6.2 | length 253.2
  Top Layer w10: R6.2@272.44,766.93 303.07,766.93 308,762 308,735 312,739 v1(312,763)
  Top Layer w20: v1(340,570) 357.01,570 385.01,598 v1(340.1,598) ; v1(340,624) 364.58,624 C14.1@387.8,600.79
  other v1: 314,736
+POC_VOLTAGE: C1.1 C4.1 C5.1 C9.1 C10.1 C13.1 J1.1 L3.2 R5.1 TR1.1 U2.5 | length 658.4
  Top Layer w20: v1(35.43,667.72) 35.43,683.28 56.98,704.83 C13.1@57.09,704.94 ; v1(57.09,667.72) C13.1@57.09,704.94 ; C13.1@58.27,706.12 C13.1@57.09,704.94 ; C10.1@523.59,123.81 C10.1@525.59,125.81 ; C4.1@590.24,55.51 590.55,55.83 v1(590.55,88.98) ; C5.1@610.2,123.81 C5.1@612.2,125.81
  Top Layer w25: v1(35.43,667.72) v1(57.09,667.72) v1(78.74,667.72) ; C13.1@58.27,706.12 58.27,688.18 67.91,678.54 v1(78.74,667.72) ; U2.5@126.77,682.28 78.74,682.28 v1(78.74,667.72)
  Bottom Layer w10: C1.1@1350.39,126.69 1351.38,127.68 TR1.1@1351.38,159.84
  Bottom Layer w15: C1.1@1350.39,126.69 1336.3,126.69 ; 1336.3,126.69 1335.63,127.36 v1(1324.8,138.19) v1(1324.8,116.54) 1334.96,126.69 1336.3,126.69
  Bottom Layer w20: v1(503.94,88.98) v1(503.94,67.32) v1(525.59,67.32) ; v1(503.94,88.98) 503.94,104.16 523.59,123.81 C9.1@525.59,125.81 ; v1(503.94,88.98) v1(525.59,88.98) ; v1(525.59,67.32) v1(547.24,67.32) v1(547.24,88.98) ; v1(525.59,67.32) v1(525.59,88.98) ; v1(525.59,88.98) C9.1@525.59,125.81 ; v1(525.59,88.98) v1(547.24,88.98) ; C9.1@525.59,125.81 547.24,104.16 v1(547.24,88.98)
  other v1: 612.2,88.98 633.86,88.98 677.17,88.98 698.82,88.98 720.47,88.98 157.48,791.73 179.13,791.73
CAM_SCL: C34.1 CN2.14 R21.2 U4.4 | length 387.7
  Top Layer w6: v1(881.89,762.2) 895.67,762.2 917.32,740.55 917.32,714.68 946.57,685.43 U4.4@968.5,685.43
  Top Layer w10: R21.2@858.58,762.2 v1(881.89,762.2)
  Bottom Layer w6: v1(881.89,762.2) 909.45,789.76 909.45,901.97 930.4,922.92 CN2.14@957.09,922.92
  Bottom Layer w10: C34.1@858.58,762.2 v1(881.89,762.2)
CAM_SDA: C33.1 CN2.12 R20.2 U4.5 | length 454.2
  Top Layer w6: v1(881.89,705.12) 908.88,705.12 948.25,665.75 U4.5@968.5,665.75
  Top Layer w10: R20.2@858.58,705.12 v1(881.89,705.12)
  Bottom Layer w6: v1(881.89,705.12) 1011.81,835.04 1011.81,901.97 1032.76,922.92 CN2.12@1057.09,922.92
  Bottom Layer w10: C33.1@858.58,705.12 v1(881.89,705.12)
DGND: C1.2 C2.2 C3.2 C4.2 C5.2 C9.2 C10.2 C13.2 C14.2 C15.2 C18.2 C19.2 C20.2 C21.2 C22.2 C23.2 C24.2 C25.2 C26.2 C27.2 C28.2 C29.2 C30.2 C31.2 C32.2 C33.2 C34.2 C35.2 C36.2 C37.1 CN1.2 CN1.3 CN1.4 CN1.5 CN2.16 CN2.18 CN2.22 CN2.31 CN2.32 D2.2 J1.2 J2.2 R8.2 R10.2 R12.2 SW1.1 SW1.2 TR1.4 U2.2 U3.6 U3.11 U4.7 U4.33 X1.2 | length 2970
  Top Layer w9.84: v1(942.91,626.38) U4.7@968.5,626.38
  Top Layer w10: v1@421.26,543.7 v1@428.46,543.03 ; U3.6@466.12,386.63 494.63,386.63 505,397 v1(505,400)
  Top Layer w15: R8.2@221.26,804.65 237.09,804.65 ; v1(248.03,793.7) 237.09,804.65 ; v1(248.03,815.35) 237.32,804.65 237.09,804.65 ; v1(629.92,29.92) 629.92,55.2 630.24,55.51 v1(653.54,55.51) ; v1(935.04,354.72) 935.04,390.72 946.28,401.97 956.69,391.56 v1(956.69,354.72) ; C23.2@978.03,480.71 978.35,480.39 v1(978.35,455.12) ; C22.2@978.03,516.14 978.03,543.39 v1(978.35,541.73) ; v1(1047.24,858.66) 1072.52,858.66 C18.2@1072.83,858.98 ; v1(1155.51,392.13) 1191.51,392.13 1202.76,403.37 1201.49,404.64 1192.35,413.78 v1(1155.51,413.78) ; C25.2@1181.42,527.95 v1(1204.72,527.95) ; v1(1200.79,779.92) 1201.1,780.24 C20.2@1201.1,805.51 ; v1(1289.37,701.18) 1320.87,701.18 v1(1320.87,734.65)
  Top Layer w20: v1(108.27,805.51) 69.29,805.51 59.25,815.55 58.27,816.52 68.92,827.17 v1(108.27,827.17) ; U2.2@244.88,682.28 245.28,682.28 ; D2.2@266.73,571.26 D2.2@277.56,571.26 ; v1(299.21,549.61) 288.39,560.43 D2.2@277.56,571.26 ; v1(299.21,571.26) D2.2@277.56,571.26 ; v1(299.21,592.91) D2.2@277.56,571.26 ; v1@421.26,543.7 v1(429.13,543.7) v1(450.79,543.7) ; C14.2@457.26,600.79 C14.2@470.47,600.79 ; v1(492.13,579.13) 481.3,589.96 C14.2@470.47,600.79 ; v1(492.13,600.79) C14.2@470.47,600.79 ; v1(492.13,622.44) C14.2@470.47,600.79 ; SW1.1@585,505.47 v1(585,576) ; v1(590.55,234.65) 590.55,219.46 C5.2@612.2,197.81 ; v1(612.2,234.65) C5.2@612.2,197.81 ; SW1.1@615.35,502.36 623,510.01 v1(623,573) ; v1(633.86,234.65) 633.86,219.46 614.2,199.81 C5.2@612.2,197.81 ; v1@677.17,372.44 677.17,355.29 696.82,335.64 C3.2@698.82,333.64 ; v1(681,574) 681,503.65 SW1.2@682.28,502.36 ; v1(698.82,372.44) C3.2@698.82,333.64 ; SW1.2@715.75,502.36 720,506.61 v1(720,575) ; v1(720.47,372.44) 720.47,355.29 700.82,335.64 C3.2@698.82,333.64 ; U4.33@1027.56,675.59 v1(1035,675.59) v2(1062.99,675.59) 1071,667.58 U4.33@1071,666 ; v1(503.94,234.65) v1(503.94,256.3) v1(525.59,256.3) ; v1(503.94,234.65) 503.94,219.46 C10.2@525.59,197.81 ; v1(503.94,234.65) v1(525.59,234.65) ; C10.2@525.59,197.81 v1(525.59,234.65) ; C10.2@525.59,197.81 527.59,199.81 547.24,219.46 v1(547.24,234.65) ; v1(525.59,234.65) v1(525.59,256.3) ; v1(525.59,234.65) v1(547.24,234.65) ; v1(525.59,256.3) v1(547.24,256.3) v1(547.24,234.65)
  Bottom Layer w15: v1(88.58,911.81) 68.2,911.81 CN2.32@57.09,922.92 69.6,935.43 v1(88.58,935.43) ; v1(88.58,1124.41) 69.6,1124.41 CN2.31@57.09,1136.92 68.2,1148.03 v1(88.58,1148.03) ; v1(724.41,911.81) 745.98,911.81 CN2.18@757.09,922.92 744.57,935.43 v1(724.41,935.43) ; v1(787.4,705.12) C33.2@818.58,705.12 ; v1(787.4,762.2) C34.2@818.58,762.2 ; v1(801.18,514.17) 826.2,514.17 838.02,525.98 826.2,537.8 v1(801.18,537.8) ; v1(824.8,911.81) 845.98,911.81 CN2.16@857.09,922.92 844.57,935.43 v1(824.8,935.43) ; R12.2@871.73,638.19 871.89,638.35 872.05,638.5 v1(872.05,671.65) ; v1(909.45,380.32) 924.63,380.32 944.28,399.97 C31.2@946.28,401.97 ; v1(909.45,401.97) C31.2@946.28,401.97 ; v1(909.45,423.62) 924.63,423.62 C31.2@946.28,401.97 ; v1(954.72,480.71) C30.2@978.03,480.71 ; v1(954.72,516.14) C29.2@978.03,516.14 ; C19.2@1072.83,858.98 1084.33,870.47 v1(1098.43,870.47) ; R10.2@1104.65,478.74 1127.95,478.74 v1(1135.83,470.87) ; C26.2@1141.73,567.64 1165.67,567.64 v1(1169.29,571.26) ; v1(1188.98,831.1) 1201.1,818.98 C21.2@1201.1,805.51 ; v1(1322.83,85.04) 1324.49,86.69 1350.39,86.69 1350.39,75.2 v1@1338.58,63.39
  Bottom Layer w20: v1(588.58,911.81) 568.2,911.81 CN2.22@557.09,922.92 569.6,935.43 v1(588.58,935.43) ; v1(503.94,234.65) v1(503.94,256.3) v1(525.59,256.3) ; v1(503.94,234.65) 503.94,219.46 C9.2@525.59,197.81 ; v1(503.94,234.65) v1(525.59,234.65) ; C9.2@525.59,197.81 v1(525.59,234.65) ; C9.2@525.59,197.81 527.59,199.81 547.24,219.46 v1(547.24,234.65) ; v1(525.59,234.65) v1(525.59,256.3) ; v1(525.59,234.65) v1(547.24,234.65) ; v1(525.59,256.3) v1(547.24,256.3) v1(547.24,234.65)
  other v1: 1337.49,58.31 1535.43,77.17 1535.43,155.91 1431.1,177.56 1431.1,199.21 1431.1,220.87 1535.43,234.65 874,311 896,311 787.4,352.76 866.14,352.76 673,373 1377.95,392.13 1456.69,392.13 787.4,431.5 866.14,431.5 1377.95,470.87 1456.69,470.87 1377.95,549.61 1456.69,549.61 1480.32,587.01 1063,648 255.91,671.65 285,672 313,672 343,672 1090,675 1063,702
  other v2: 1062.99,625.59 1012.99,675.59 1112.99,675.59 1062.99,725.59
DIN0: CN2.24 U4.19 | length 1050.3
  Top Layer w6: U4.19@1157.48,646.06 v1(1202.76,646.06)
  Bottom Layer w6: CN2.24@457.09,922.92 481.02,922.92 501.97,901.97 501.97,866.54 519.68,848.82 519.68,720.87 568.9,671.65 692.91,671.65 777.56,587.01 940.94,587.01 944.88,590.94 1127.95,590.94 1183.07,646.06 v1(1202.76,646.06)
DIN1: CN2.23 U4.20 | length 1215.5
  Top Layer w6: U4.20@1157.48,665.75 v1(1185.04,665.75)
  Bottom Layer w6: CN2.23@457.09,1136.92 481.58,1136.92 494.09,1124.41 494.09,1035.83 515.75,1014.17 515.75,870.47 533.46,852.76 533.46,724.8 572.83,685.43 696.85,685.43 781.5,600.79 937.01,600.79 940.94,604.72 1124.02,604.72 v1(1185.04,665.75)
DIN2: CN2.2 U4.21 | length 503.2
  Top Layer w6: U4.21@1157.48,685.43 1194.88,685.43 1342.52,833.07 1444.88,833.07 1503.94,892.13 1503.94,900 v1(1527.56,923.62)
  Bottom Layer w10: v1(1527.56,923.62) 1556.39,923.62 CN2.2@1557.09,922.92
DIN3: CN2.1 U4.22 | length 798.9
  Top Layer w6: U4.22@1157.48,705.12 1196.85,705.12 1344.49,852.76 v1(1437.01,852.76)
  Bottom Layer w6: v1(1437.01,852.76) 1570.87,852.76 1590.55,872.44 1590.55,1134.45 1588.08,1136.92 CN2.1@1557.09,1136.92
DIN4: CN2.4 U4.23 | length 382.3
  Top Layer w6: U4.23@1157.48,724.8 1198.82,724.8 1397.64,923.62 v1(1427.17,923.62)
  Bottom Layer w10: v1(1427.17,923.62) 1456.39,923.62 CN2.4@1457.09,922.92
DIN5: CN2.3 U4.24 | length 559
  Top Layer w6: U4.24@1157.48,744.49 1200.79,744.49 1407.48,951.18 1407.48,1116.54 v1(1427.17,1136.22)
  Bottom Layer w10: v1(1427.17,1136.22) 1456.39,1136.22 CN2.3@1457.09,1136.92
DIN6: CN2.6 U4.26 | length 333
  Top Layer w6: U4.26@1112.2,770.08 1112.2,801.57 1118.11,807.48 1118.11,817.32 1151.57,850.79 1253.94,850.79 v1(1326.77,923.62)
  Bottom Layer w10: v1(1326.77,923.62) 1356.39,923.62 CN2.6@1357.09,922.92
DIN7: CN2.5 U4.27 | length 553.7
  Top Layer w6: U4.27@1092.52,770.08 1092.52,803.54 1100.39,811.42 1100.39,817.32 1147.64,864.57 1250,864.57 1307.09,921.65 1307.09,1116.54 v1(1326.77,1136.22)
  Bottom Layer w10: v1(1326.77,1136.22) 1327.47,1136.92 CN2.5@1357.09,1136.92
DIN8: CN2.8 U4.29 | length 370.9
  Top Layer w6: U4.29@1053.15,770.08 1053.15,797.64 1027.56,823.23 1027.56,884.25 1041.34,898.03 1200.79,898.03 v1(1226.38,923.62)
  Bottom Layer w10: v1(1226.38,923.62) 1256.39,923.62 CN2.8@1257.09,922.92
DIN9: CN2.7 U4.30 | length 605.1
  Top Layer w6: U4.30@1033.46,770.08 1033.46,799.61 1013.78,819.29 1013.78,888.19 1023.62,898.03 1023.62,1122.44 1039.37,1138.19 v1(1226.38,1138.19)
  Bottom Layer w10: v1(1226.38,1138.19) 1255.82,1138.19 CN2.7@1257.09,1136.92
DOUTP_F: C17.1 CN1.1 L4.2 TR1.3 | length 669.3
  Top Layer w8: C17.1@1102.36,478.43 1102.36,455.12 1127.95,429.53 1127.95,252.36 1181.1,199.21 CN1.1@1311.02,199.21
  Bottom Layer w15: CN1.1@1311.02,199.21 TR1.3@1351.38,199.21
  Bottom Layer w40: L4.2@1124.02,199.78 1310.46,199.78 CN1.1@1311.02,199.21
GPIO0: CN2.10 R19.2 U4.15 | length 755.9
  Top Layer w6: U4.15@1112.2,581.1 1112.2,570.8 1131.43,551.57 1200.79,551.57 1204.72,547.64 1277.56,547.64 1291.34,533.86 v1(1301.18,533.86)
  Top Layer w10: v1(1106.3,949.21) R19.2@1106.3,972.52
  Bottom Layer w6: v1(1106.3,949.21) 1132.59,922.92 CN2.10@1157.09,922.92 1168.02,922.92 1244.09,846.85 1244.09,588.98 1299.21,533.86 v1(1301.18,533.86)
GPIO1: CN2.9 R18.2 U4.16 | length 977.7
  Top Layer w6: U4.16@1131.89,581.1 1145.67,581.1 1155.51,590.94 1179.13,590.94 1208.66,561.42 1299.21,561.42 v1(1301.18,559.45)
  Top Layer w10: R18.2@1106.3,1087.32 v1(1106.3,1110.63)
  Bottom Layer w6: v1(1106.3,1110.63) 1132.59,1136.92 CN2.9@1157.09,1136.92 1157.79,1136.22 1181.1,1136.22 1206.69,1110.63 1206.69,1069.29 1244.09,1031.89 1275.59,1031.89 1307.09,1000.39 1307.09,775.98 1344.49,738.58 1344.49,600.79 1303.15,559.45 v1(1301.18,559.45)
HSYNC: CN2.13 U4.1 | length 453.7
  Top Layer w6: U4.1@968.5,744.49 968.5,787.8 1000,819.29 1000,892.13 1009.84,901.97 1009.84,1120.47 992.13,1138.19 v1(988.19,1138.19)
  Bottom Layer w10: CN2.13@957.09,1136.92 958.35,1138.19 v1(988.19,1138.19)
